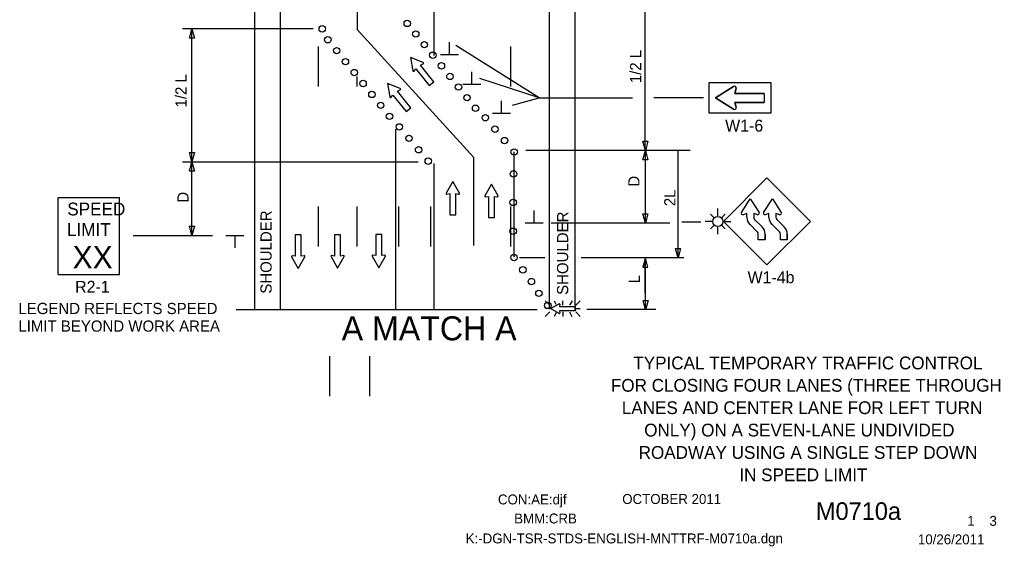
# Model space of a CAD drawing. Extents: x 16731 to 19504, y 5932 to 7446.
# Drawn here: x 16792 to 17404, y 5932 to 6261 of the extents above; entities that cross this region are included whole.
import ezdxf

# ---------------------------------------------------------------- set-up
doc = ezdxf.new("R2010")
doc.units = 0
for name, color, linetype in [('ALI_LEGAL_EX', 7, 'Continuous'), ('BORDER_SIGNAL_WO', 7, 'Continuous'), ('MT_SCRATCH_LEVEL_E', 7, 'Continuous'), ('PAVT_EDGE_EX', 7, 'Continuous'), ('TRAFFIC_SIGNS_PR', 7, 'Continuous'), ('TYPICAL_EX', 7, 'Continuous'), ('TYPICAL_TEXT_DIMEN_PR', 7, 'Continuous')]:
    doc.layers.add(name, color=color, linetype=linetype)

msp = doc.modelspace()

# ---------------------------------------------------------------- linework, layer by layer
at = {"layer": 'ALI_LEGAL_EX'}
for points in [[(16978.71, 6219.12), (16978.71, 6244.12)], [(17098.71, 6219.12), (17098.71, 6244.12)], [(17002.71, 6219.12), (17002.71, 6225.28)], [(17075.62, 6119.76), (17075.62, 6174.72)], [(16978.71, 6119.12), (16978.71, 6144.12)], [(17002.71, 6119.12), (17002.71, 6144.12)], [(17028.71, 6119.12), (17028.71, 6144.12)], [(17048.71, 6119.12), (17048.71, 6144.12)], [(17098.71, 6119.12), (17098.71, 6144.12)]]:
    msp.add_lwpolyline(points, dxfattribs=at)
at = {"layer": 'MT_SCRATCH_LEVEL_E'}
for p, q in [((17036.14, 6237.18), (17037.48, 6228.96)), ((17043.92, 6234.14), (17036.14, 6237.18)), ((17036.14, 6237.18), (17037.48, 6228.96)), ((17043.92, 6234.14), (17036.14, 6237.18)), ((17038.29, 6228.73), (17039.47, 6230.09)), ((17038.29, 6228.73), (17039.47, 6230.09)), ((17039.47, 6230.09), (17047.79, 6219.77)), ((17039.47, 6230.09), (17047.79, 6219.77)), ((17042.39, 6232.44), (17043.97, 6233.31)), ((17042.39, 6232.44), (17043.97, 6233.31)), ((17050.7, 6222.11), (17042.39, 6232.44)), ((17050.7, 6222.11), (17042.39, 6232.44)), ((17047.79, 6219.77), (17050.7, 6222.11)), ((17047.79, 6219.77), (17050.7, 6222.11)), ((17021.81, 6220.88), (17023.15, 6212.66)), ((17029.58, 6217.84), (17021.81, 6220.88)), ((17021.81, 6220.88), (17023.15, 6212.66)), ((17029.58, 6217.84), (17021.81, 6220.88)), ((17028.05, 6216.14), (17029.64, 6217.01)), ((17028.05, 6216.14), (17029.64, 6217.01)), ((17036.37, 6205.81), (17028.05, 6216.14)), ((17036.37, 6205.81), (17028.05, 6216.14)), ((17023.95, 6212.43), (17025.14, 6213.79)), ((17023.95, 6212.43), (17025.14, 6213.79)), ((17025.14, 6213.79), (17033.45, 6203.46)), ((17025.14, 6213.79), (17033.45, 6203.46)), ((17033.45, 6203.46), (17036.37, 6205.81)), ((17033.45, 6203.46), (17036.37, 6205.81)), ((17062.47, 6159.81), (17058.36, 6152.57)), ((17062.47, 6159.81), (17058.36, 6152.57)), ((17066.62, 6152.57), (17062.47, 6159.81)), ((17066.62, 6152.57), (17062.47, 6159.81)), ((17086.57, 6158.1), (17082.46, 6150.86)), ((17086.57, 6158.1), (17082.46, 6150.86)), ((17090.72, 6150.86), (17086.57, 6158.1)), ((17090.72, 6150.86), (17086.57, 6158.1)), ((17058.85, 6151.89), (17060.62, 6152.2)), ((17058.85, 6151.89), (17060.62, 6152.2)), ((17060.62, 6152.2), (17060.62, 6138.94)), ((17060.62, 6152.2), (17060.62, 6138.94)), ((17064.36, 6138.94), (17064.36, 6152.2)), ((17064.36, 6152.2), (17066.14, 6151.89)), ((17064.36, 6138.94), (17064.36, 6152.2)), ((17064.36, 6152.2), (17066.14, 6151.89)), ((17082.94, 6150.17), (17084.72, 6150.49)), ((17082.94, 6150.17), (17084.72, 6150.49)), ((17084.72, 6150.49), (17084.72, 6137.23)), ((17084.72, 6150.49), (17084.72, 6137.23)), ((17088.46, 6137.23), (17088.46, 6150.49)), ((17088.46, 6150.49), (17090.24, 6150.17)), ((17088.46, 6137.23), (17088.46, 6150.49)), ((17088.46, 6150.49), (17090.24, 6150.17)), ((17060.62, 6138.94), (17064.36, 6138.94)), ((17060.62, 6138.94), (17064.36, 6138.94)), ((17084.72, 6137.23), (17088.46, 6137.23)), ((17084.72, 6137.23), (17088.46, 6137.23)), ((16967.87, 6126.36), (16964.13, 6126.36)), ((16964.13, 6126.36), (16964.13, 6113.11)), ((16967.87, 6126.36), (16964.13, 6126.36)), ((16964.13, 6126.36), (16964.13, 6113.11)), ((16967.87, 6113.11), (16967.87, 6126.36)), ((16967.87, 6113.11), (16967.87, 6126.36)), ((16992.45, 6126.46), (16988.71, 6126.46)), ((16988.71, 6126.46), (16988.71, 6113.2)), ((16992.45, 6126.46), (16988.71, 6126.46)), ((16988.71, 6126.46), (16988.71, 6113.2)), ((16992.45, 6113.2), (16992.45, 6126.46)), ((16992.45, 6113.2), (16992.45, 6126.46)), ((17018.13, 6126.72), (17014.39, 6126.72)), ((17014.39, 6126.72), (17014.39, 6113.46)), ((17018.13, 6126.72), (17014.39, 6126.72)), ((17014.39, 6126.72), (17014.39, 6113.46)), ((17018.13, 6113.46), (17018.13, 6126.72)), ((17018.13, 6113.46), (17018.13, 6126.72)), ((16961.87, 6112.74), (16966.02, 6105.5)), ((16961.87, 6112.74), (16966.02, 6105.5)), ((16964.13, 6113.11), (16962.35, 6113.42)), ((16964.13, 6113.11), (16962.35, 6113.42)), ((16966.02, 6105.5), (16970.13, 6112.74)), ((16966.02, 6105.5), (16970.13, 6112.74)), ((16969.65, 6113.42), (16967.87, 6113.11)), ((16969.65, 6113.42), (16967.87, 6113.11)), ((16986.45, 6112.84), (16990.6, 6105.6)), ((16986.45, 6112.84), (16990.6, 6105.6)), ((16988.71, 6113.2), (16986.93, 6113.52)), ((16988.71, 6113.2), (16986.93, 6113.52)), ((16990.6, 6105.6), (16994.71, 6112.84)), ((16990.6, 6105.6), (16994.71, 6112.84)), ((16994.23, 6113.52), (16992.45, 6113.2)), ((16994.23, 6113.52), (16992.45, 6113.2)), ((17012.13, 6113.09), (17016.28, 6105.85)), ((17012.13, 6113.09), (17016.28, 6105.85)), ((17014.39, 6113.46), (17012.61, 6113.78)), ((17014.39, 6113.46), (17012.61, 6113.78)), ((17016.28, 6105.85), (17020.39, 6113.09)), ((17016.28, 6105.85), (17020.39, 6113.09)), ((17019.91, 6113.78), (17018.13, 6113.46)), ((17019.91, 6113.78), (17018.13, 6113.46))]:
    msp.add_line(p, q, dxfattribs=at)
for centre, start, end in [((17037.94, 6229.04), 189.26563, 318.8046), ((17037.94, 6229.04), 189.26563, 318.8046), ((17043.74, 6233.71), 298.87699, 68.61391), ((17043.74, 6233.71), 298.87699, 68.61391), ((17029.4, 6217.41), 298.87699, 68.61391), ((17029.4, 6217.41), 298.87699, 68.61391), ((17023.61, 6212.74), 189.26563, 318.8046), ((17023.61, 6212.74), 189.26563, 318.8046), ((17058.77, 6152.35), 150.42484, 279.96381), ((17058.77, 6152.35), 150.42484, 279.96381), ((17066.21, 6152.35), 260.03619, 29.77312), ((17066.21, 6152.35), 260.03619, 29.77312), ((17082.87, 6150.63), 150.42484, 279.96381), ((17082.87, 6150.63), 150.42484, 279.96381), ((17090.31, 6150.63), 260.03619, 29.77312), ((17090.31, 6150.63), 260.03619, 29.77312), ((16962.28, 6112.96), 80.03619, 209.77312), ((16962.28, 6112.96), 80.03619, 209.77312), ((16969.72, 6112.96), 330.42484, 99.96381), ((16969.72, 6112.96), 330.42484, 99.96381), ((16986.86, 6113.06), 80.03619, 209.77312), ((16986.86, 6113.06), 80.03619, 209.77312), ((16994.3, 6113.06), 330.42484, 99.96381), ((16994.3, 6113.06), 330.42484, 99.96381), ((17012.54, 6113.32), 80.03619, 209.77312), ((17012.54, 6113.32), 80.03619, 209.77312), ((17019.98, 6113.32), 330.42484, 99.96381), ((17019.98, 6113.32), 330.42484, 99.96381)]:
    msp.add_arc(centre, 0.463, start, end, dxfattribs=at)
at = {"layer": 'PAVT_EDGE_EX'}
for p, q in [((16954.71, 6865.32), (16954.71, 6079.93)), ((17122.71, 6865.32), (17122.71, 6079.93)), ((17138.71, 6865.32), (17138.71, 6112.72)), ((16938.71, 6770.67), (16938.71, 6079.72)), ((17002.71, 6439.27), (17002.71, 6254.65)), ((17050.71, 6415.36), (17050.71, 6238.46)), ((17026.71, 6192.44), (17026.71, 6079.72)), ((17050.71, 6170.95), (17050.71, 6080.14)), ((17138.71, 6112.72), (17138.71, 6079.72))]:
    msp.add_line(p, q, dxfattribs=at)
for points in [[(16985.78, 6025.74), (16985.78, 6050.74)], [(16985.78, 6025.74), (16985.78, 6050.74)], [(17010.78, 6025.74), (17010.78, 6050.74)], [(17010.78, 6025.74), (17010.78, 6050.74)]]:
    msp.add_lwpolyline(points, dxfattribs=at)
at = {"layer": 'TRAFFIC_SIGNS_PR'}
for p, q in [((17237.78, 6219.08), (17226.62, 6211.98)), ((17238.63, 6214.78), (17239.47, 6217.84)), ((17226.62, 6211.98), (17237.78, 6204.87)), ((17257.02, 6214.78), (17238.63, 6214.78)), ((17257.02, 6214.78), (17257.02, 6209.18)), ((17239.47, 6206.11), (17238.63, 6209.18)), ((17238.63, 6209.18), (17257.02, 6209.18)), ((17231.46, 6134.81), (17258.61, 6161.97)), ((17258.61, 6161.97), (17285.76, 6134.81)), ((16815.99, 6149.71), (16854.39, 6149.71)), ((16815.99, 6101.71), (16815.99, 6149.71)), ((16854.39, 6101.71), (16854.39, 6149.71)), ((17227.97, 6138.32), (17227.97, 6142.82)), ((17225.46, 6137.28), (17223.35, 6139.39)), ((17230.48, 6137.28), (17232.59, 6139.39)), ((17224.82, 6134.77), (17219.98, 6134.77)), ((17225.46, 6132.25), (17223.35, 6130.15)), ((17227.97, 6126.8), (17227.97, 6131.21)), ((17230.48, 6132.25), (17232.59, 6130.15)), ((17231.12, 6134.77), (17236.01, 6134.77)), ((17258.61, 6107.66), (17231.46, 6134.81)), ((17252.63, 6128.3), (17247.91, 6133.01)), ((17252.63, 6128.3), (17247.91, 6133.01)), ((17255.68, 6131.35), (17250.97, 6136.06)), ((17250.97, 6136.06), (17255.68, 6131.35)), ((17285.76, 6134.81), (17258.61, 6107.66)), ((17266.42, 6128.3), (17261.71, 6133.01)), ((17266.42, 6128.3), (17261.71, 6133.01)), ((17269.48, 6131.35), (17264.76, 6136.06)), ((17264.76, 6136.06), (17269.48, 6131.35)), ((17253.23, 6123.23), (17253.23, 6126.93)), ((17257.55, 6123.23), (17257.55, 6126.93)), ((17267.03, 6123.23), (17267.03, 6126.93)), ((17271.34, 6123.23), (17271.34, 6126.93)), ((17257.55, 6123.23), (17253.23, 6123.23)), ((17271.34, 6123.23), (17267.03, 6123.23)), ((16815.99, 6101.71), (16854.39, 6101.71)), ((17120.25, 6085.24), (17123.07, 6082.42)), ((17125.69, 6085.24), (17126.89, 6083.15)), ((17131.15, 6082.42), (17131.15, 6085.24)), ((17136.94, 6085.24), (17135.31, 6082.42)), ((17139.24, 6082.42), (17142.06, 6085.24)), ((17123.07, 6080.39), (17120.25, 6080.39)), ((17120.25, 6075.54), (17123.07, 6078.36)), ((17126.97, 6077.72), (17125.71, 6075.54)), ((17131.15, 6078.36), (17131.15, 6075.54)), ((17135.29, 6078.36), (17136.92, 6075.54)), ((17139.24, 6080.39), (17142.06, 6080.39)), ((17139.24, 6078.36), (17142.06, 6075.54))]:
    msp.add_line(p, q, dxfattribs=at)
msp.add_lwpolyline([(17261.02, 6202.38), (17222.62, 6202.38), (17222.62, 6221.57), (17261.02, 6221.57)], close=True, dxfattribs=at)
for points in [[(17237.78, 6204.87), (17226.62, 6211.98), (17237.78, 6219.08)], [(17239.47, 6217.84), (17238.63, 6214.78), (17257.02, 6214.78), (17257.02, 6209.18), (17238.63, 6209.18), (17239.47, 6206.11)], [(17242.76, 6140.34), (17248.24, 6148.95), (17253.72, 6140.34)], [(17242.76, 6140.34), (17248.24, 6148.95), (17253.72, 6140.34)], [(17256.56, 6140.34), (17262.04, 6148.95), (17267.52, 6140.34)], [(17256.56, 6140.34), (17262.04, 6148.95), (17267.52, 6140.34)], [(17246.09, 6137.32), (17246.09, 6139.69), (17243.72, 6139.04)], [(17246.09, 6137.32), (17246.09, 6139.69), (17243.72, 6139.04)], [(17252.76, 6139.04), (17250.4, 6139.69), (17250.41, 6137.39)], [(17252.76, 6139.04), (17251.93, 6139.27), (17250.4, 6139.69), (17250.41, 6137.39)], [(17259.89, 6137.32), (17259.88, 6139.69), (17257.52, 6139.04)], [(17259.89, 6137.32), (17259.88, 6139.69), (17257.52, 6139.04)], [(17266.56, 6139.04), (17264.2, 6139.69), (17264.2, 6137.39)], [(17266.56, 6139.04), (17265.72, 6139.27), (17264.2, 6139.69), (17264.2, 6137.39)], [(17257.55, 6126.93), (17257.55, 6123.23), (17253.23, 6123.23), (17253.23, 6126.93)], [(17271.34, 6126.93), (17271.34, 6123.23), (17267.03, 6123.23), (17267.03, 6126.93)], [(17128.83, 6077.38), (17123.52, 6080.39), (17128.83, 6083.43)], [(17129.33, 6083.07), (17129.1, 6081.78), (17138.82, 6081.78), (17138.82, 6079.03), (17129.1, 6079.03), (17129.33, 6077.73)]]:
    msp.add_lwpolyline(points, dxfattribs=at)
for centre, radius in [((17034.04, 6258.5), 2), ((16980.95, 6255.13), 2), ((17039.38, 6251.88), 2), ((16984.47, 6248.3), 2), ((17044.71, 6245.25), 2), ((16989.97, 6241.47), 2), ((17050.04, 6238.63), 2), ((16995.47, 6234.64), 2), ((17000.97, 6227.81), 2), ((17055.38, 6232.01), 2), ((17006.47, 6220.97), 2), ((17060.71, 6225.38), 2), ((17011.97, 6214.14), 2), ((17066.04, 6218.76), 2), ((17071.38, 6212.14), 2), ((17017.47, 6207.31), 2), ((17076.71, 6205.51), 2), ((17022.97, 6200.48), 2), ((17082.81, 6199.58), 2), ((17082.81, 6199.58), 2), ((17029.14, 6193.86), 2), ((17029.14, 6193.86), 2), ((17088.81, 6192.44), 2), ((17035.14, 6186.72), 2), ((17094.81, 6185.3), 2), ((17041.14, 6179.58), 2), ((17100.81, 6178.16), 2), ((17047.14, 6172.44), 2), ((17100.41, 6164.49), 2), ((17100.19, 6146.69), 2), ((17227.97, 6134.77), 3.15), ((17100.19, 6128.69), 2), ((17100.73, 6112.25), 2), ((17106.24, 6104.59), 2), ((17111.58, 6097.24), 2), ((17116.26, 6089.9), 2), ((17121.82, 6082.34), 2)]:
    msp.add_circle(centre, radius, dxfattribs=at)
for centre, radius, start, end in [((17238.38, 6218.13), 1.12, 344.67308, 122.46963), ((17238.38, 6218.13), 1.12, 344.67308, 122.46962), ((17238.38, 6205.82), 1.12, 237.53038, 15.32692), ((17238.38, 6205.82), 1.12, 237.53038, 15.32692), ((17243.49, 6139.88), 0.866, 147.7292, 285.31719), ((17243.49, 6139.88), 0.866, 147.71964, 285.32011), ((17233.65, 6146.13), 10.8, 327.53351, 327.54311), ((17246.57, 6128.62), 10.8, 105.31922, 105.32004), ((17252.26, 6137.39), 6.17, 180.61811, 225.78746), ((17252.26, 6137.39), 6.17, 180.62445, 225.23128), ((17252.26, 6137.39), 1.85, 180, 225.78746), ((17252.26, 6137.39), 1.85, 179.8762, 225.7877), ((17252.99, 6139.87), 0.864, 254.6014, 32.47956), ((17252.99, 6139.87), 0.866, 254.61481, 32.47119), ((17257.29, 6139.88), 0.866, 147.7292, 285.31719), ((17257.29, 6139.88), 0.866, 147.71964, 285.32011), ((17247.45, 6146.13), 10.8, 327.53351, 327.54311), ((17260.37, 6128.62), 10.8, 105.31922, 105.32004), ((17266.05, 6137.39), 6.17, 180.61811, 225.78746), ((17266.05, 6137.39), 6.17, 180.62445, 225.23128), ((17266.05, 6137.39), 1.85, 180, 225.78746), ((17266.05, 6137.39), 1.85, 179.8762, 225.7877), ((17266.79, 6139.87), 0.864, 254.6014, 32.47956), ((17266.79, 6139.87), 0.866, 254.61481, 32.47119), ((17251.38, 6126.93), 6.17, 0, 45.78746), ((17251.38, 6126.93), 6.17, 0, 45.78746), ((17251.38, 6126.93), 6.17, 0, 45.78828), ((17265.18, 6126.93), 6.17, 0, 45.78746), ((17265.18, 6126.93), 6.17, 0, 45.78746), ((17265.18, 6126.93), 6.17, 0, 45.78828), ((17251.38, 6126.93), 1.85, 0, 47.62801), ((17251.38, 6126.93), 1.85, 0, 45.78746), ((17265.18, 6126.93), 1.85, 0, 47.62801), ((17265.18, 6126.93), 1.85, 0, 45.78746), ((17128.99, 6083.13), 0.341, 350.04067, 118.51671), ((17128.99, 6077.67), 0.341, 241.10835, 9.26922)]:
    msp.add_arc(centre, radius, start, end, dxfattribs=at)
at = {"layer": 'TYPICAL_EX'}
msp.add_line((16938.71, 6865.32), (16938.71, 6080.34), dxfattribs=at)
at = {"layer": 'TYPICAL_TEXT_DIMEN_PR'}
for p, q in [((17182.71, 6179.17), (17182.71, 6267.12)), ((16975.25, 6255.13), (16893.7, 6255.13)), ((16898.02, 6249.26), (16899.59, 6255.13)), ((16899.59, 6172.09), (16899.59, 6255.13)), ((16899.59, 6255.13), (16901.16, 6249.26)), ((17002.71, 6254.65), (17075.64, 6174.71)), ((16899.59, 6249.26), (16898.02, 6249.26)), ((16901.16, 6249.26), (16899.59, 6249.26)), ((17060.43, 6238.94), (17060.43, 6246.72)), ((17116.4, 6211.96), (17064.46, 6244.63)), ((17066.05, 6238.94), (17054.8, 6238.94)), ((17074.36, 6220.37), (17074.36, 6228.16)), ((17116.4, 6211.96), (17079.43, 6224.02)), ((17079.98, 6220.37), (17068.73, 6220.37)), ((17092.91, 6202.29), (17092.91, 6210.08)), ((17099.67, 6207.54), (17116.4, 6211.96)), ((17116.4, 6211.96), (17174.71, 6211.96)), ((17187.93, 6212.18), (17219.11, 6212.18)), ((17098.53, 6202.29), (17087.28, 6202.29)), ((17182.74, 6179.15), (17181.17, 6185.02)), ((17181.17, 6185.02), (17182.74, 6185.02)), ((17181.17, 6173.31), (17182.74, 6179.17)), ((17182.74, 6185.02), (17184.31, 6185.02)), ((17184.31, 6185.02), (17182.74, 6179.15)), ((17182.74, 6179.17), (17184.31, 6173.31)), ((16899.62, 6172.07), (16898.06, 6177.94)), ((16898.06, 6177.94), (16899.62, 6177.94)), ((16899.62, 6177.94), (16901.19, 6177.94)), ((16901.19, 6177.94), (16899.62, 6172.07)), ((17100.6, 6178.28), (17100.6, 6112.56)), ((17210.8, 6179.15), (17108.13, 6179.15)), ((17182.74, 6173.31), (17181.17, 6173.31)), ((17184.31, 6173.31), (17182.74, 6173.31)), ((17182.75, 6133.9), (17182.75, 6179.15)), ((17203.14, 6112.66), (17203.14, 6178.73)), ((16893.7, 6172.07), (17040.9, 6172.07)), ((16898.06, 6166.21), (16899.62, 6172.07)), ((16899.62, 6172.07), (16901.19, 6166.21)), ((16899.63, 6126.23), (16899.63, 6171.48)), ((16899.62, 6166.21), (16898.06, 6166.21)), ((16901.19, 6166.21), (16899.62, 6166.21)), ((17113.38, 6133.77), (17113.38, 6141.56)), ((17182.75, 6133.8), (17181.18, 6139.66)), ((17181.18, 6139.66), (17182.75, 6139.66)), ((17182.75, 6139.66), (17184.32, 6139.66)), ((17184.32, 6139.66), (17182.75, 6133.8)), ((16899.63, 6126.03), (16898.06, 6131.89)), ((16898.06, 6131.89), (16899.63, 6131.89)), ((16899.63, 6131.89), (16901.2, 6131.89)), ((16901.2, 6131.89), (16899.63, 6126.03)), ((17119.01, 6133.77), (17107.76, 6133.77)), ((17197.98, 6133.82), (17123.97, 6133.82)), ((17217.35, 6134.4), (17205.45, 6134.4)), ((16862.82, 6126.05), (16912.46, 6126.05)), ((16920.82, 6126.03), (16932.07, 6126.03)), ((16926.44, 6126.03), (16926.44, 6118.25)), ((17119.91, 6112.01), (17104.16, 6112.01)), ((17206.84, 6112.01), (17142.6, 6112.01)), ((17182.75, 6112.01), (17181.18, 6106.15)), ((17182.73, 6079.65), (17182.73, 6111.93)), ((17184.32, 6106.15), (17182.75, 6112.01)), ((17203.18, 6111.98), (17201.61, 6117.84)), ((17201.61, 6117.84), (17203.18, 6117.84)), ((17203.18, 6117.84), (17204.75, 6117.84)), ((17204.75, 6117.84), (17203.18, 6111.98)), ((17181.18, 6106.15), (17182.75, 6106.15)), ((17182.71, 6090.25), (17182.71, 6111.5)), ((17182.75, 6106.15), (17184.32, 6106.15)), ((17182.86, 6079.57), (17181.29, 6085.43)), ((17181.29, 6085.43), (17182.86, 6085.43)), ((17182.86, 6085.43), (17184.43, 6085.43)), ((17184.43, 6085.43), (17182.86, 6079.57)), ((16927.17, 6079.72), (17115.16, 6079.72)), ((17189.17, 6079.72), (17146.21, 6079.72))]:
    msp.add_line(p, q, dxfattribs=at)

# ---------------------------------------------------------------- texts
at = {"layer": 'BORDER_SIGNAL_WO'}
for s, height, p in [('TYPICAL TEMPORARY TRAFFIC CONTROL', 7.9737, (17175.21, 6042.43)), ('FOR CLOSING FOUR LANES (THREE THROUGH', 7.9737, (17161.21, 6028.45)), ('LANES AND CENTER LANE FOR LEFT TURN', 7.9737, (17168.04, 6014.48)), ('ONLY) ON A SEVEN-LANE UNDIVIDED', 7.9737, (17182.02, 6000.5)), ('ROADWAY USING A SINGLE STEP DOWN', 7.9737, (17178.54, 5986.53)), ('IN SPEED LIMIT', 7.9737, (17241.42, 5972.55)), ('CON:AE:djf', 6.2, (17090.69, 5958.06)), ('    OCTOBER 2011    ', 6.2, (17159.08, 5958.34)), ('    M0710a   ', 11, (17272.86, 5948.38)), ('BMM:CRB   ', 6.2, (17100.81, 5946.17)), (' 1    3 ', 6.2, (17381.45, 5944.7)), ('K:-DGN-TSR-STDS-ENGLISH-MNTTRF-M0710a.dgn        ', 6.2, (17070.55, 5933.71)), ('10/26/2011    ', 6.2, (17352.93, 5933.13))]:
    msp.add_text(s, height=height, dxfattribs=at).set_placement(p)
at = {"layer": 'TRAFFIC_SIGNS_PR'}
for s, height, p in [('W1-6', 7.44, (17232.56, 6190.94)), ('SPEED', 8, (16821.76, 6138.57)), ('LIMIT', 8, (16821.6, 6125.77)), ('XX', 14.031, (16825.11, 6105.47)), ('W1-4b', 7.44, (17246.56, 6096.22)), ('R2-1', 7.44, (16826.67, 6090.27))]:
    msp.add_text(s, height=height, dxfattribs=at).set_placement(p)
at = {"layer": 'TYPICAL_TEXT_DIMEN_PR'}
for s, p in [('1/2 L', (17180.15, 6221.18)), ('1/2 L', (16896.3, 6205.99)), ('D', (17179.06, 6156.5)), ('D', (16897.53, 6146.53)), ('2L', (17201.5, 6144.35)), ('SHOULDER', (16949.4, 6089.67)), ('SHOULDER', (17134.55, 6088.95)), ('L', (17179.37, 6096.15))]:
    msp.add_text(s, height=7, rotation=90, dxfattribs=at).set_placement(p)
for s, height, p in [('LEGEND REFLECTS SPEED', 7, (16791.24, 6076.95)), ('A MATCH A', 15, (16993.12, 6060.55)), ('LIMIT BEYOND WORK AREA', 7, (16791.24, 6065.95))]:
    msp.add_text(s, height=height, dxfattribs=at).set_placement(p)

doc.saveas('drawing.dxf')
